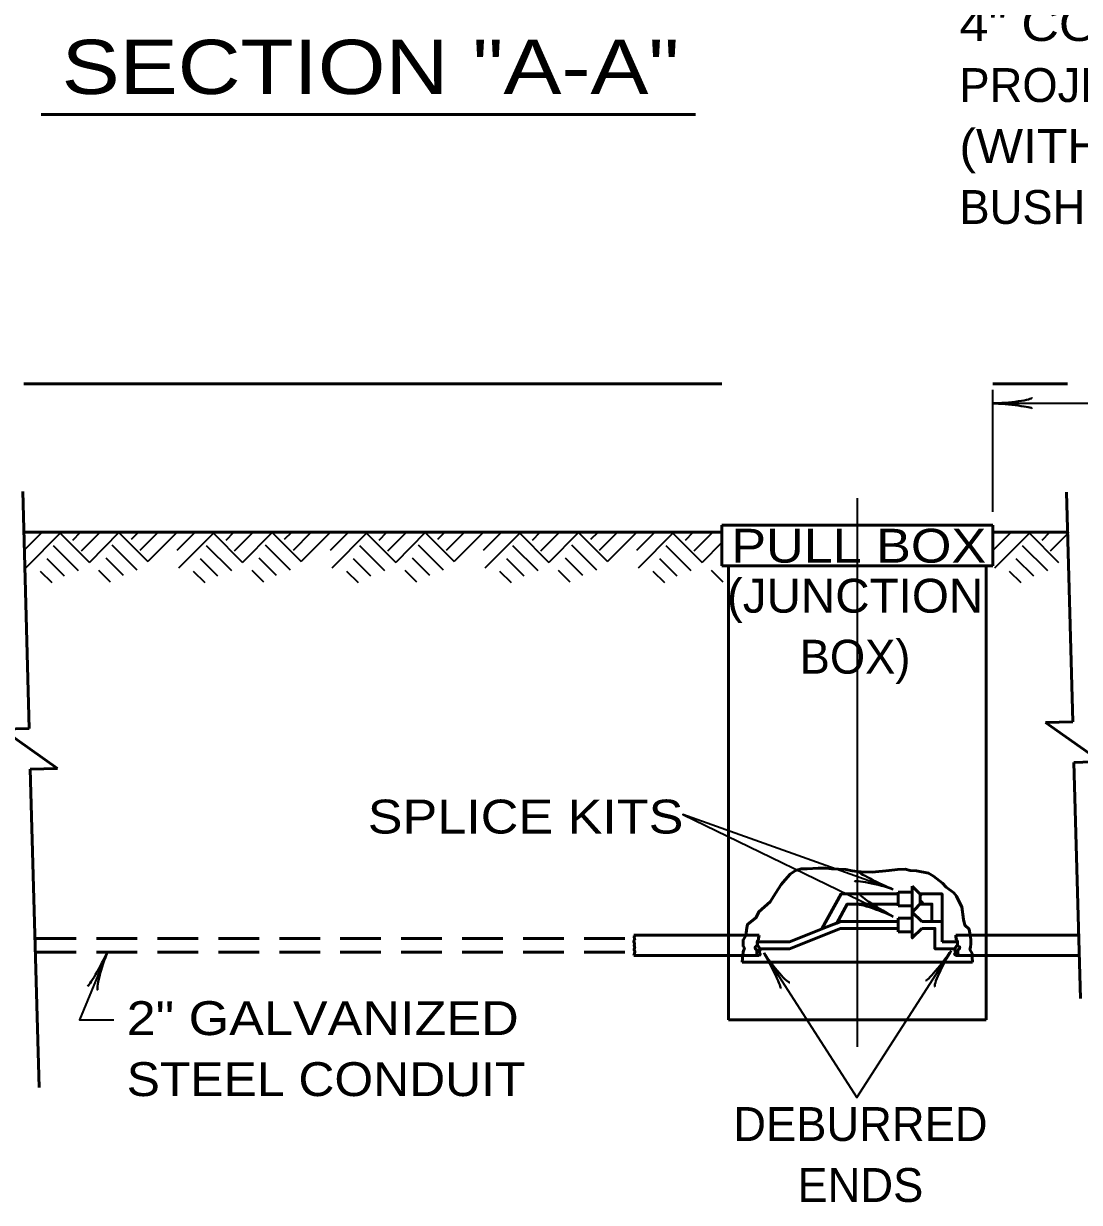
# Model space of a CAD drawing. Extents: x -68 to 612, y -58 to 382.
# Drawn here: x 75.5 to 153.4, y 126.8 to 213.8 of the extents above; entities that cross this region are included whole.
import ezdxf
from ezdxf.enums import TextEntityAlignment as Align

# ---------------------------------------------------------------- set-up
doc = ezdxf.new("R2010")
doc.units = 0
doc.linetypes.add('MEDIUM_DASHED', pattern=[4.5, 3, -1.5])
doc.layers.add('1', color=7, linetype='Continuous', lineweight=53)

msp = doc.modelspace()

# ---------------------------------------------------------------- linework, layer by layer
at = {"layer": '1'}
for p, q in [((76.783, 207.083), (125.073, 207.083)), ((75.507, 187.207), (127.007, 187.207)), ((147.007, 187.207), (152.507, 187.207)), ((75.424, 179.274), (75.906, 161.775)), ((152.426, 179.206), (152.892, 162.275)), ((127.007, 173.775), (127.007, 176.775)), ((127.007, 176.775), (147.007, 176.775)), ((147.007, 173.775), (147.007, 176.775)), ((75.507, 176.275), (127.007, 176.275)), ((147.007, 176.275), (152.507, 176.275)), ((127.007, 173.775), (147.007, 173.775)), ((127.507, 173.775), (127.507, 140.275)), ((146.507, 173.775), (146.507, 140.275)), ((150.893, 162.22), (152.892, 162.275)), ((150.893, 162.22), (154.974, 159.331)), ((73.906, 161.72), (75.906, 161.775)), ((73.906, 161.72), (77.987, 158.831)), ((152.974, 159.276), (154.974, 159.331)), ((152.974, 159.276), (153.454, 141.839)), ((75.988, 158.776), (77.987, 158.831)), ((75.988, 158.776), (76.634, 135.279)), ((140.006, 149.69), (141.05, 149.69)), ((141.763, 149.434), (141.05, 150.147)), ((141.05, 148.232), (141.05, 150.147)), ((141.843, 149.026), (141.05, 148.232)), ((140.006, 148.69), (141.05, 148.69)), ((141.757, 147.525), (141.05, 148.232)), ((132.007, 146.025), (135.757, 147.525)), ((140.006, 147.525), (135.757, 147.525)), ((140.006, 147.775), (140.006, 146.775)), ((140.006, 147.775), (141.05, 147.775)), ((143.257, 147.525), (141.757, 147.525)), ((143.257, 146.025), (143.257, 147.525)), ((120.507, 146.525), (129.757, 146.525)), ((132.007, 145.525), (135.757, 147.025)), ((140.006, 147.025), (135.757, 147.025)), ((140.006, 146.775), (141.05, 146.775)), ((153.325, 146.525), (144.257, 146.525)), ((129.586, 146.025), (132.007, 146.025)), ((129.857, 145.525), (132.007, 145.525)), ((144.428, 146.025), (143.257, 146.025)), ((120.507, 145.025), (129.757, 145.025)), ((145.507, 144.525), (128.507, 144.525)), ((153.366, 145.025), (144.257, 145.025)), ((127.507, 140.275), (146.507, 140.275))]:
    msp.add_line(p, q, dxfattribs=at)
at = {"layer": '1', "lineweight": 35}
for p, q in [((147.007, 177.775), (147.007, 186.775)), ((147.007, 185.775), (178.866, 185.775)), ((137.007, 138.275), (137.007, 178.775)), ((76.827, 176.235), (75.507, 174.915)), ((78.247, 176.235), (75.627, 173.615)), ((78.147, 176.235), (80.347, 174.035)), ((79.667, 176.235), (79.107, 175.655)), ((81.107, 176.235), (79.727, 174.855)), ((82.527, 176.235), (80.347, 174.035)), ((82.527, 176.235), (84.667, 174.095)), ((83.947, 176.235), (83.427, 175.715)), ((85.387, 176.235), (84.067, 174.915)), ((86.807, 176.235), (84.667, 174.095)), ((88.127, 176.235), (86.807, 174.915)), ((89.547, 176.235), (86.927, 173.615)), ((89.447, 176.235), (91.647, 174.035)), ((90.967, 176.235), (90.407, 175.655)), ((92.407, 176.235), (91.027, 174.855)), ((93.827, 176.235), (91.647, 174.035)), ((93.827, 176.235), (95.967, 174.095)), ((95.247, 176.235), (94.727, 175.715)), ((96.687, 176.235), (95.367, 174.915)), ((98.107, 176.235), (95.967, 174.095)), ((99.427, 176.235), (98.107, 174.915)), ((100.847, 176.235), (98.227, 173.615)), ((100.747, 176.235), (102.947, 174.035)), ((102.267, 176.235), (101.707, 175.655)), ((103.707, 176.235), (102.327, 174.855)), ((105.127, 176.235), (102.947, 174.035)), ((105.127, 176.235), (107.267, 174.095)), ((106.547, 176.235), (106.027, 175.715)), ((107.987, 176.235), (106.667, 174.915)), ((109.407, 176.235), (107.267, 174.095)), ((110.727, 176.235), (109.407, 174.915)), ((112.147, 176.235), (109.527, 173.615)), ((112.047, 176.235), (114.247, 174.035)), ((113.567, 176.235), (113.007, 175.655)), ((115.007, 176.235), (113.627, 174.855)), ((116.427, 176.235), (114.247, 174.035)), ((116.427, 176.235), (118.567, 174.095)), ((117.847, 176.235), (117.327, 175.715)), ((119.287, 176.235), (117.967, 174.915)), ((120.707, 176.235), (118.567, 174.095)), ((122.027, 176.235), (120.707, 174.915)), ((123.447, 176.235), (120.827, 173.615)), ((123.347, 176.235), (125.547, 174.035)), ((124.867, 176.235), (124.307, 175.655)), ((126.307, 176.235), (124.927, 174.855)), ((148.327, 176.235), (147.007, 174.915)), ((149.747, 176.235), (147.127, 173.615)), ((149.647, 176.235), (151.847, 174.035)), ((151.167, 176.235), (150.607, 175.655)), ((152.607, 176.235), (151.227, 174.855)), ((77.667, 175.275), (79.527, 173.435)), ((82.007, 175.335), (83.847, 173.495)), ((88.967, 175.275), (90.827, 173.435)), ((93.307, 175.335), (95.147, 173.495)), ((100.267, 175.275), (102.127, 173.435)), ((104.607, 175.335), (106.447, 173.495)), ((111.567, 175.275), (113.427, 173.435)), ((115.907, 175.335), (117.747, 173.495)), ((122.867, 175.275), (124.727, 173.435)), ((127.007, 175.509), (125.547, 174.035)), ((149.167, 175.275), (151.027, 173.435)), ((77.207, 174.315), (78.487, 173.035)), ((81.547, 174.375), (82.827, 173.095)), ((88.507, 174.315), (89.787, 173.035)), ((92.847, 174.375), (94.127, 173.095)), ((99.807, 174.315), (101.087, 173.035)), ((104.147, 174.375), (105.427, 173.095)), ((111.107, 174.315), (112.387, 173.035)), ((115.447, 174.375), (116.727, 173.095)), ((122.407, 174.315), (123.687, 173.035)), ((148.707, 174.315), (149.987, 173.035)), ((76.707, 173.395), (77.567, 172.555)), ((81.027, 173.455), (81.887, 172.595)), ((88.007, 173.395), (88.867, 172.555)), ((92.327, 173.455), (93.187, 172.595)), ((99.307, 173.395), (100.167, 172.555)), ((103.627, 173.455), (104.487, 172.595)), ((110.607, 173.395), (111.467, 172.555)), ((114.927, 173.455), (115.787, 172.595)), ((121.907, 173.395), (122.767, 172.555)), ((126.227, 173.455), (127.087, 172.595)), ((148.207, 173.395), (149.067, 172.555))]:
    msp.add_line(p, q, dxfattribs=at)
at = {"layer": '1', "linetype": 'MEDIUM_DASHED'}
for p, q in [((76.359, 146.275), (120.591, 146.275)), ((76.359, 145.275), (120.627, 145.275))]:
    msp.add_line(p, q, dxfattribs=at)
at = {"layer": '1', "lineweight": 35}
for points in [[(139.647, 149.904), (124.136, 155.42), (139.647, 147.894)], [(130.113, 145.213), (136.967, 134.542), (143.924, 145.368)], [(81.674, 145.275), (79.605, 140.279), (82.145, 140.279)]]:
    msp.add_lwpolyline(points, dxfattribs=at)
at = {"layer": '1'}
for points in [[(128.507, 144.525), (128.573, 145.297), (128.673, 145.562), (128.573, 145.728), (128.573, 146.159), (128.772, 146.49), (128.838, 147.053), (128.904, 147.319), (129.534, 147.816), (129.733, 148.247), (130.561, 148.976), (130.992, 149.639), (131.39, 150.269), (131.688, 150.6), (132.053, 151.031), (132.45, 151.297), (132.881, 151.429), (133.312, 151.429), (134.107, 151.462), (134.67, 151.462), (135.101, 151.429), (136.162, 151.363), (136.626, 151.263), (136.99, 151.23), (137.288, 151.197), (138.084, 151.164), (139.343, 151.297), (139.972, 151.363), (140.536, 151.396), (140.9, 151.297), (141.364, 151.263), (142.259, 151.098), (142.624, 150.866), (143.286, 150.368), (143.551, 150.07), (144.115, 149.639), (144.314, 149.407), (144.479, 149.042), (144.711, 148.612), (144.844, 147.683), (144.943, 147.252), (145.241, 146.954), (145.308, 146.656), (145.341, 146.49), (145.374, 146.092), (145.374, 145.893), (145.341, 145.628), (145.308, 145.462), (145.473, 145.164), (145.473, 144.899), (145.507, 144.525)], [(140.006, 149.69), (140.006, 148.815), (140.006, 148.69)], [(141.632, 149.565), (143.257, 149.565), (143.257, 147.525)], [(141.757, 147.025), (141.05, 146.318), (141.05, 148.232)], [(120.507, 146.525), (120.553, 146.451), (120.535, 146.374), (120.564, 146.285), (120.582, 146.255), (120.553, 146.19), (120.535, 146.149), (120.511, 146.042), (120.558, 145.93), (120.553, 145.835), (120.535, 145.776), (120.553, 145.67), (120.582, 145.581), (120.547, 145.528), (120.529, 145.439), (120.582, 145.35), (120.594, 145.279), (120.57, 145.226), (120.553, 145.161), (120.507, 145.025)], [(129.757, 146.525), (129.746, 146.374), (129.698, 146.314), (129.722, 146.22), (129.639, 146.102), (129.628, 146.09), (129.616, 146.007), (129.616, 145.96), (129.628, 145.889), (129.628, 145.806), (129.545, 145.699), (129.474, 145.652), (129.462, 145.628), (129.474, 145.534), (129.568, 145.439), (129.592, 145.427), (129.592, 145.38), (129.592, 145.155), (129.568, 145.12), (129.568, 145.084), (129.58, 145.025)], [(144.157, 145.525), (142.723, 145.525), (142.723, 147.025), (141.757, 147.025)], [(144.257, 146.525), (144.268, 146.374), (144.315, 146.314), (144.292, 146.22), (144.375, 146.102), (144.386, 146.09), (144.398, 146.007), (144.398, 145.96), (144.386, 145.889), (144.386, 145.806), (144.469, 145.699), (144.54, 145.652), (144.552, 145.628), (144.54, 145.534), (144.446, 145.439), (144.422, 145.427), (144.422, 145.38), (144.422, 145.155), (144.446, 145.12), (144.446, 145.084), (144.434, 145.025)], [(129.757, 145.025), (129.84, 145.108), (129.829, 145.179), (129.781, 145.25), (129.793, 145.333), (129.829, 145.439), (129.793, 145.546), (129.769, 145.617), (129.722, 145.676), (129.639, 145.759), (129.604, 145.794)], [(144.257, 145.025), (144.174, 145.108), (144.185, 145.179), (144.233, 145.25), (144.221, 145.333), (144.185, 145.439), (144.221, 145.546), (144.244, 145.617), (144.292, 145.676), (144.375, 145.759), (144.41, 145.794)]]:
    msp.add_lwpolyline(points, dxfattribs=at)
for points in [[(135.487, 147.418), (134.39, 146.979), (135.812, 149.565), (140.006, 149.565), (140.006, 148.815), (136.256, 148.815), (135.487, 147.417), (135.757, 147.525)], [(141.632, 149.565), (141.632, 148.815), (142.507, 148.815), (142.507, 147.525), (143.257, 147.525), (143.257, 149.565)]]:
    msp.add_lwpolyline(points, close=True, dxfattribs=at)
at = {"layer": '1', "lineweight": 40}
for centre, major_axis, ratio, start_param, end_param in [((148.098, 186.052), (-1.786, -0.156), 0.122415, 0.896353, 3.141593), ((148.098, 186.052), (-1.786, -0.156), 0.122415, 0.896353, 3.141593), ((148.128, 185.564), (-1.756, 0.176), 0.07063, 3.140715, 5.41811), ((148.128, 185.564), (-1.756, 0.176), 0.07063, 3.140715, 5.41811), ((138.526, 150.01), (1.735, -0.451), 0.122415, 0.896353, 3.141593), ((138.662, 150.479), (-1.596, 0.754), 0.07063, 6.282307, 8.559703), ((138.545, 148.122), (1.675, -0.639), 0.122415, 0.896353, 3.141593), ((138.731, 148.573), (1.504, -0.925), 0.07063, 3.140715, 5.41811), ((143.141, 144.54), (-1.097, -1.383), 0.07063, 6.282307, 8.559703), ((143.567, 144.301), (0.834, 1.587), 0.122415, 0.896353, 3.141593), ((81.05, 144.321), (-0.834, -1.556), 0.07063, 6.282307, 8.559703), ((81.512, 144.162), (0.539, 1.71), 0.122415, 0.896353, 3.141593), ((130.541, 144.156), (0.801, -1.573), 0.07063, 6.282307, 8.559703), ((130.541, 144.156), (0.801, -1.573), 0.07063, 6.282307, 8.559703), ((130.936, 144.444), (-1.096, 1.418), 0.122415, 0.896353, 3.141593), ((130.936, 144.444), (-1.096, 1.418), 0.122415, 0.896353, 3.141593)]:
    msp.add_ellipse(centre, major_axis=major_axis, ratio=ratio, start_param=start_param, end_param=end_param, dxfattribs=at)

# ---------------------------------------------------------------- texts
at = {"layer": '1'}
for s, width, p in [('4" CONDUIT', 1.15, (144.532, 212.513)), ('(WITH INSULATED', 1.1, (144.532, 203.513)), ('PULL BOX', 1.15, (127.705, 174.015)), ('SPLICE KITS', 1.15, (100.882, 154.025)), ('2" GALVANIZED', 1.15, (83.096, 139.148)), ('STEEL CONDUIT', 1.1, (83.096, 134.648))]:
    msp.add_text(s, height=2.5, dxfattribs=dict(at, width=width)).set_placement(p)
for s, height, width, p in [('SECTION "A-A"', 4, 1.2, (101.084, 208.604)), ('(JUNCTION', 2.5, 1.05, (136.835, 170.324))]:
    msp.add_text(s, height=height, dxfattribs=dict(at, width=width)).set_placement(p, align=Align.CENTER)
for s, p in [('PROJECTION', (144.532, 208.013)), ('BUSHING)', (144.532, 199.013))]:
    msp.add_text(s, height=2.5, dxfattribs=at).set_placement(p)
for s, p in [('BOX)', (136.834, 165.824)), ('DEBURRED', (137.228, 131.334)), ('ENDS', (137.228, 126.834))]:
    msp.add_text(s, height=2.5, dxfattribs=at).set_placement(p, align=Align.CENTER)

doc.saveas('drawing.dxf')
